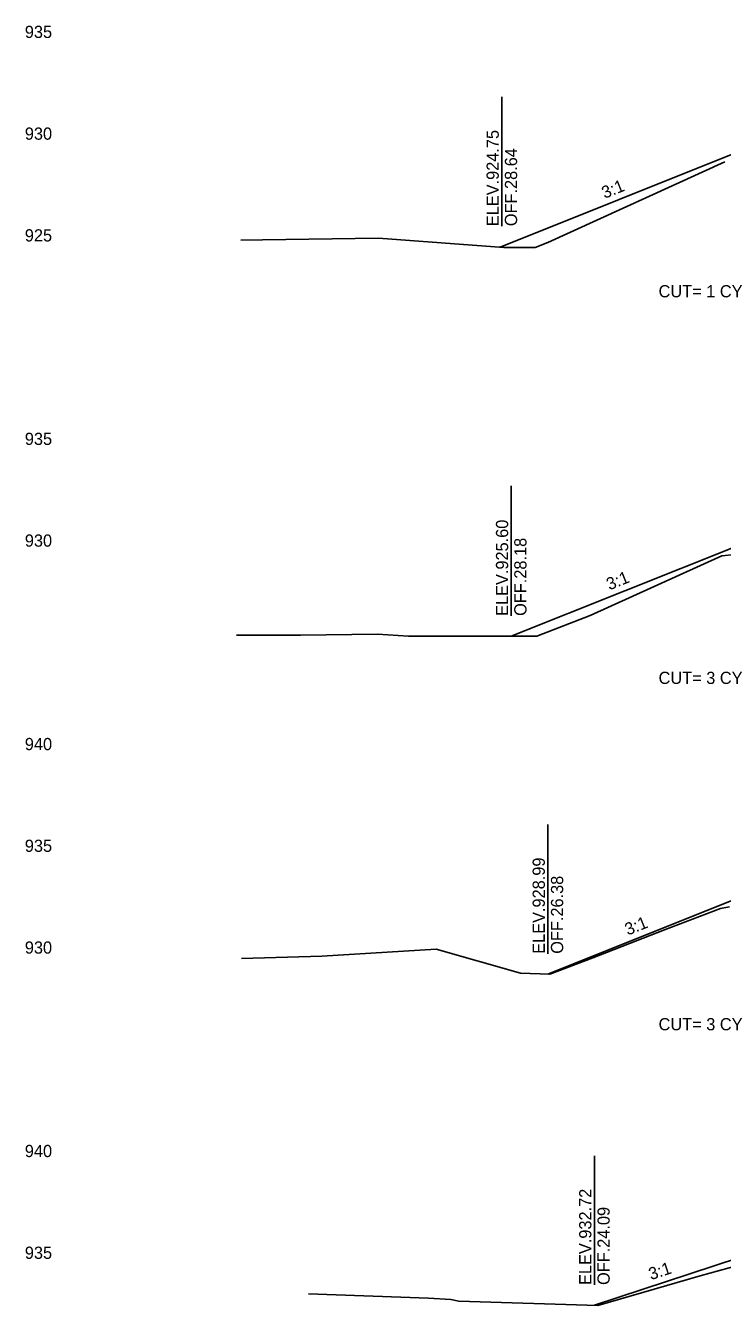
# Model space of a CAD drawing. Extents: x -4 to 359, y 0 to 1436.
# Drawn here: x 200.5 to 234.7, y 927.7 to 990.6 of the extents above; entities that cross this region are included whole.
import ezdxf

# ---------------------------------------------------------------- set-up
doc = ezdxf.new("R2010")
doc.units = 0
for name, color, linetype in [('XS-Existing surface-ground', 7, 'Continuous'), ('XS-Proposed surface-ground', 7, 'Continuous'), ('XS-Text-ditch slope', 7, 'Continuous'), ('XS-Text-earthwork labels', 7, 'Continuous'), ('XS-Text-elevation', 7, 'Continuous'), ('XS-Text-profile report', 7, 'Continuous'), ('XS-Text-tie elevation', 7, 'Continuous'), ('XS-Text-tie offset', 7, 'Continuous')]:
    doc.layers.add(name, color=color, linetype=linetype)

msp = doc.modelspace()

# ---------------------------------------------------------------- linework, layer by layer
at = {"layer": 'XS-Existing surface-ground'}
for p, q in [((226.12, 979.928), (234.817, 983.88)), ((211.034, 980.033), (212.096, 980.05)), ((212.096, 980.05), (217.793, 980.133)), ((217.793, 980.133), (223.951, 979.68)), ((223.951, 979.68), (225.486, 979.682)), ((225.486, 979.682), (226.12, 979.928)), ((228.189, 961.586), (234.669, 964.53)), ((234.669, 964.53), (235.31, 964.581)), ((225.581, 960.573), (228.189, 961.586)), ((210.822, 960.63), (213.973, 960.626)), ((213.973, 960.626), (217.741, 960.681)), ((217.741, 960.681), (219.271, 960.569)), ((219.271, 960.569), (225.581, 960.573)), ((234.592, 947.198), (235.044, 947.275)), ((231.84, 946.146), (234.592, 947.198)), ((228.324, 944.769), (231.84, 946.146)), ((211.068, 944.726), (215.016, 944.851)), ((215.016, 944.851), (220.629, 945.2)), ((220.629, 945.2), (224.772, 944.021)), ((226.214, 943.962), (228.324, 944.769)), ((224.772, 944.021), (226.214, 943.962)), ((233.596, 929.131), (235.503, 929.661)), ((228.574, 927.685), (233.596, 929.131)), ((214.36, 928.248), (220.25, 928.037)), ((220.25, 928.037), (221.35, 927.976)), ((221.35, 927.976), (221.746, 927.898)), ((221.746, 927.898), (228.574, 927.685))]:
    msp.add_line(p, q, dxfattribs=at)
at = {"layer": 'XS-Proposed surface-ground'}
for points in [[(235.474, 984.371), (223.779, 979.693)], [(235.484, 965.039), (224.317, 960.572)], [(235.49, 947.714), (226.119, 943.966)], [(235.478, 930.024), (228.405, 927.69)]]:
    msp.add_lwpolyline(points, dxfattribs=at)
at = {"layer": 'XS-Text-tie offset'}
for p, q in [((223.856, 980.724), (223.856, 987.076)), ((224.317, 961.572), (224.317, 967.97)), ((226.119, 944.966), (226.119, 951.316)), ((228.405, 928.69), (228.405, 935.04))]:
    msp.add_line(p, q, dxfattribs=at)

# ---------------------------------------------------------------- texts
at = {"layer": 'XS-Text-ditch slope'}
for rotation, p in [(21.80141, (228.904, 982.066)), (21.80141, (229.139, 962.824)), (21.80141, (230.043, 945.858)), (18.26289, (231.183, 928.923))]:
    msp.add_text('3:1', height=0.6, rotation=rotation, dxfattribs=at).set_placement(p)
at = {"layer": 'XS-Text-earthwork labels'}
for s, p in [(' CUT= 1 CY           ', (231.335, 977.227)), (' CUT= 3 CY           ', (231.335, 958.226)), (' CUT= 3 CY           ', (231.335, 941.204))]:
    msp.add_text(s, height=0.6, dxfattribs=at).set_placement(p)
at = {"layer": 'XS-Text-elevation'}
for s, p in [('           935           ', (197.97, 989.973)), ('           930           ', (197.97, 984.973)), ('           925           ', (197.97, 979.973)), ('           935           ', (197.97, 969.973)), ('           930           ', (197.97, 964.973)), ('           940           ', (197.97, 954.973)), ('           935           ', (197.97, 949.973)), ('           930           ', (197.97, 944.973)), ('           940           ', (197.97, 934.973)), ('           935           ', (197.97, 929.973))]:
    msp.add_text(s, height=0.6, dxfattribs=at).set_placement(p)
at = {"layer": 'XS-Text-profile report'}
for p in [(223.768, 979.692), (224.305, 960.572), (226.108, 943.965), (228.394, 927.689)]:
    msp.add_text('Fill_Slope_2_B', height=0.00167, dxfattribs=at).set_placement(p)
at = {"layer": 'XS-Text-tie elevation'}
for s, p in [('ELEV.924.75', (223.706, 980.724)), ('OFF.28.64', (224.606, 980.724)), ('ELEV.925.60', (224.167, 961.572)), ('OFF.28.18', (225.067, 961.572)), ('ELEV.928.99', (225.969, 944.966)), ('OFF.26.38', (226.869, 944.966)), ('ELEV.932.72', (228.255, 928.69)), ('OFF.24.09', (229.155, 928.69))]:
    msp.add_text(s, height=0.6, rotation=90, dxfattribs=at).set_placement(p)

doc.saveas('drawing.dxf')
